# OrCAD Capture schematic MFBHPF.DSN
size A
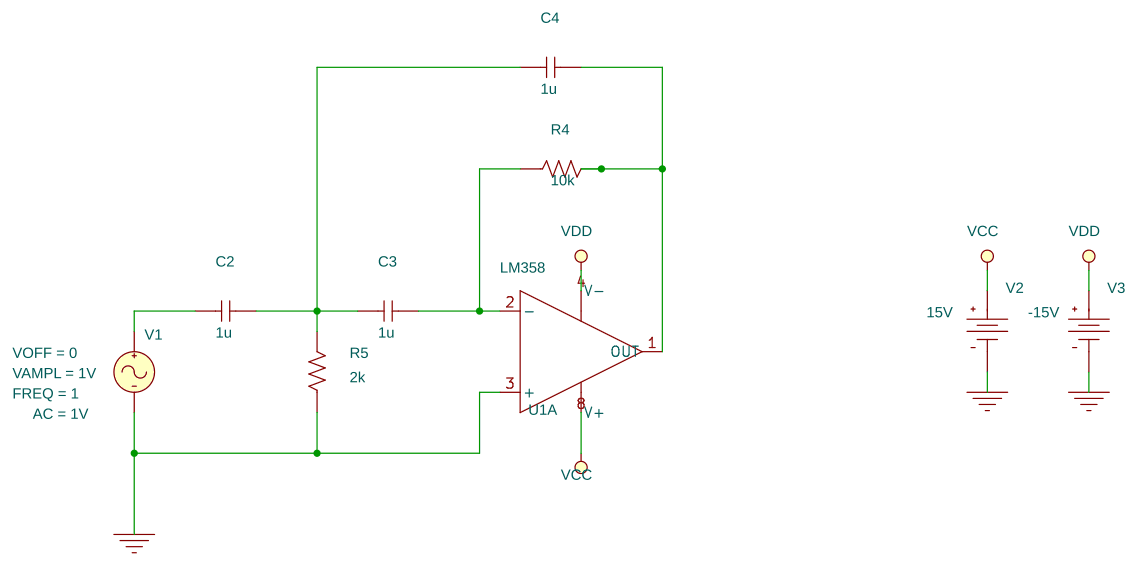
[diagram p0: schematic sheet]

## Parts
C2  1u  [cap196]
C3  1u  [cap196]
C4  1u  [cap196]
R4  10k  [AXRC05]
R5  2k  [AXRC05]
U1  LM358  [DIP1008W300L450]  (section A)
V1  VSIN
V2  VDC
V3  VDC

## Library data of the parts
C2-C4 = C
R4 R5 = R
U1 = LM358
V1 = VSIN: AC: 1V; FREQ: 1; VAMPL: 1V; VOFF: 0
V2 = VDC: DC: 15V
V3 = VDC: DC: -15V

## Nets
VCC: U1.8(V+) V2.0(+)
VDD: U1.4(V-) V3.0(+)
0: R5.1 U1.3(+) V1.2(-) V2.1(-) V3.1(-)
N02864: C2.1 C3.2 C4.2 R5.2
N02874: C4.1 R4.2 U1.1(OUT)
N02900: C3.1 R4.1 U1.2(-)
N03078: C2.2 V1.1(+)
